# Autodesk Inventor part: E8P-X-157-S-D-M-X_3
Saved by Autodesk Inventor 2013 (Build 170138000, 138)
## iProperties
Created: 2012-07
Part Number: E8P-X-157-S-D-M-X_3
Material: Allgemein
Document SubType Name: Modeling
Designer: rYan
Density: 1 g/cm^3
Mass: 0.0624434 g
Surface Area: 2.40166 cm^2
Volume: 0.0624434 cm^3
Author: rYan
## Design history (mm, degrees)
node "E8P-X-157-S-D-M-X_31"
node "E8P-X-157-S-D-M-X_3"
node "Basis1"
